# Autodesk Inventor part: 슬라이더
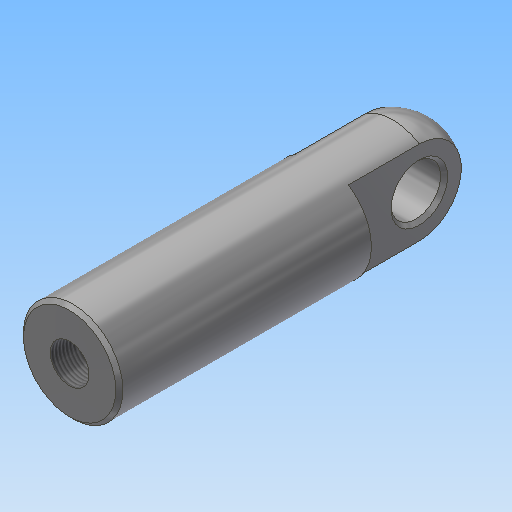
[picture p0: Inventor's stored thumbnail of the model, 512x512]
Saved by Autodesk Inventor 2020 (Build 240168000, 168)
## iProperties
Created: 2010-03
Part Number: 슬라이더
Document SubType Name: Modeling
Designer: Administrator
Density: 1 g/cm^3
Material: 강철, 연강
Appearance: 강철
Author: Administrator
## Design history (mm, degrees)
sketch "스케치1"
  geometry: C1 r 14 at (0, 0); 1 further point
  constraints: 1 centre point, 1 coincident
  dimensions: "d2" = 28 diameter of C1
extrude "돌출1" new body sketch "스케치1" distance "d0" = 105; taper "d1" = 0 deg
chamfer "모따기1" distance "d3" = 1; stored, may be unused: second distance "d4" = 2, angle "d5" = 45 deg
sketch "스케치2"
  geometry: L1 (-7.5, 11.822)-(-7.5, -11.822); L2 (7.5, 11.822)-(7.5, -11.822); A1 r 14 centre (0, 0) between (-7.5, 11.822) and (7.5, 11.822) reference
  constraints: 4 end point, 4 point on circle, 2 vertical
  dimensions: "d6" = 15 distance between parallel lines of L2 L1; "d7" = 7.5 distance from line of A1.centre L2
extrude "돌출2" cut sketch "스케치2" distance "d8" = 34; taper "d9" = 0 deg
fillet "모깎기1" dims "d10" = 14
sketch "스케치3"
  geometry: C1 r 7 at (20, 11.822); A1 r 11.822 centre (20, 11.822) between (20, 0) and (20, 23.643) reference; 1 further point
  constraints: 1 centre point, 1 coincident
  dimensions: "d11" = 14 diameter of C1
extrude "돌출3" cut sketch "스케치3" extent not by distance; stored distance "d12" = 25; taper "d13" = 0 deg
hole "구멍1" diameter "d16" = 10.917; stored, may be unused: countersink angle "d20" = 90 deg, drill point angle "d22" = 118 deg; dims "d14" = 10, "d15" = 10, "d17" = 15, "d18" = 4, "d19" = 2, "d21" = 20
chamfer "모따기2" distance "d23" = 1; stored, may be unused: second distance "d24" = 2, angle "d25" = 45 deg
node "솔리드1"
